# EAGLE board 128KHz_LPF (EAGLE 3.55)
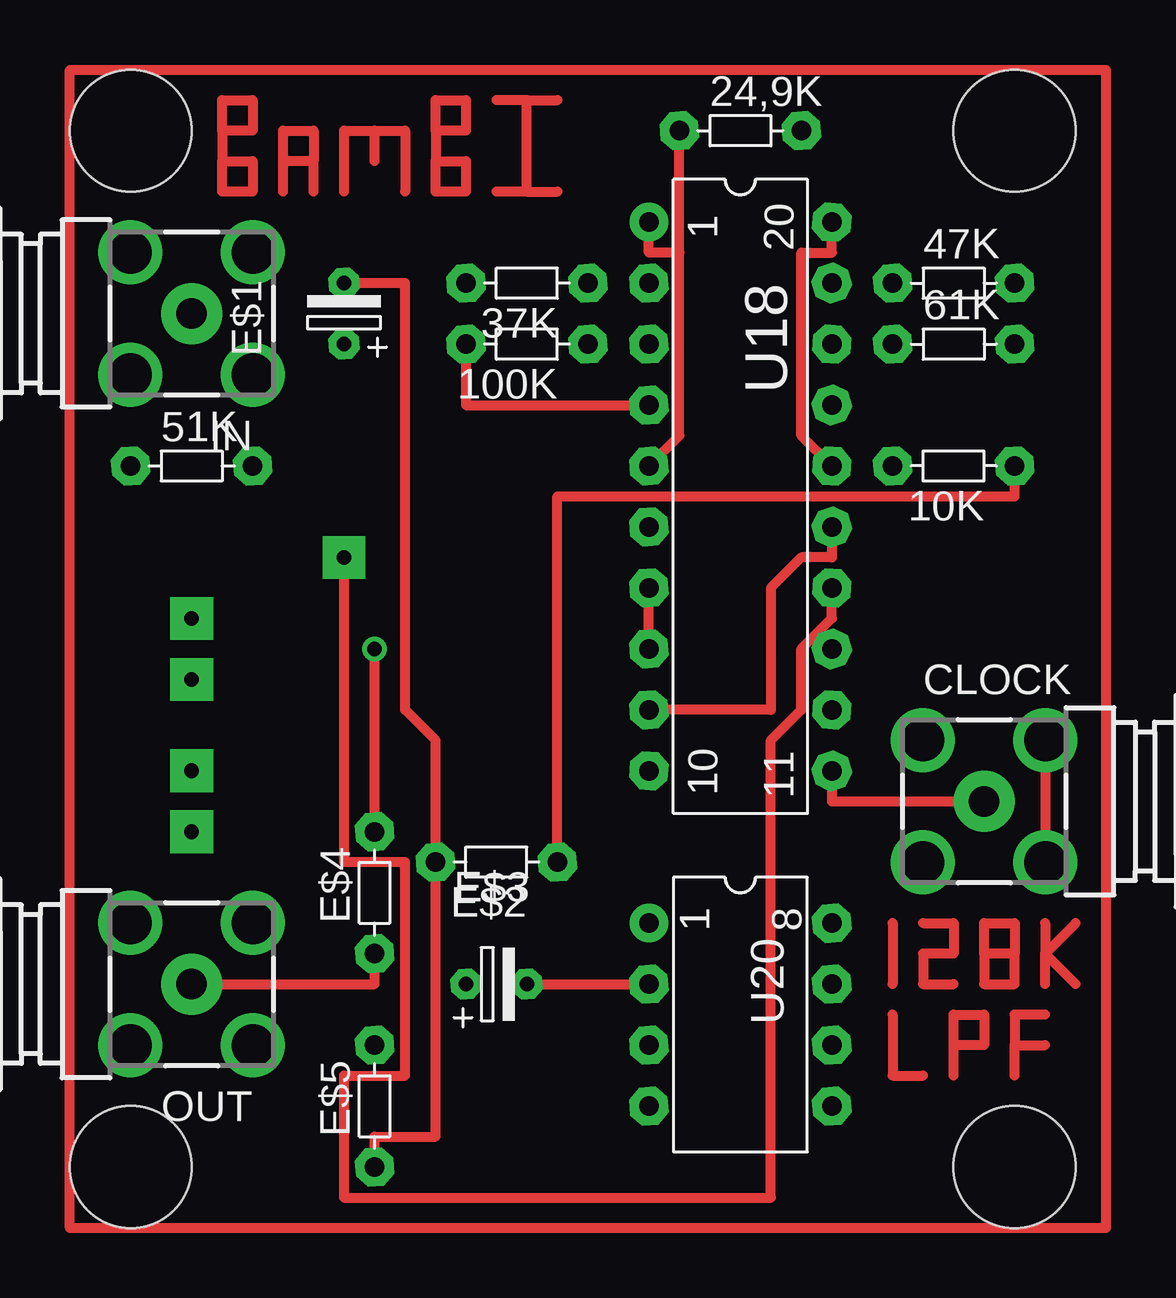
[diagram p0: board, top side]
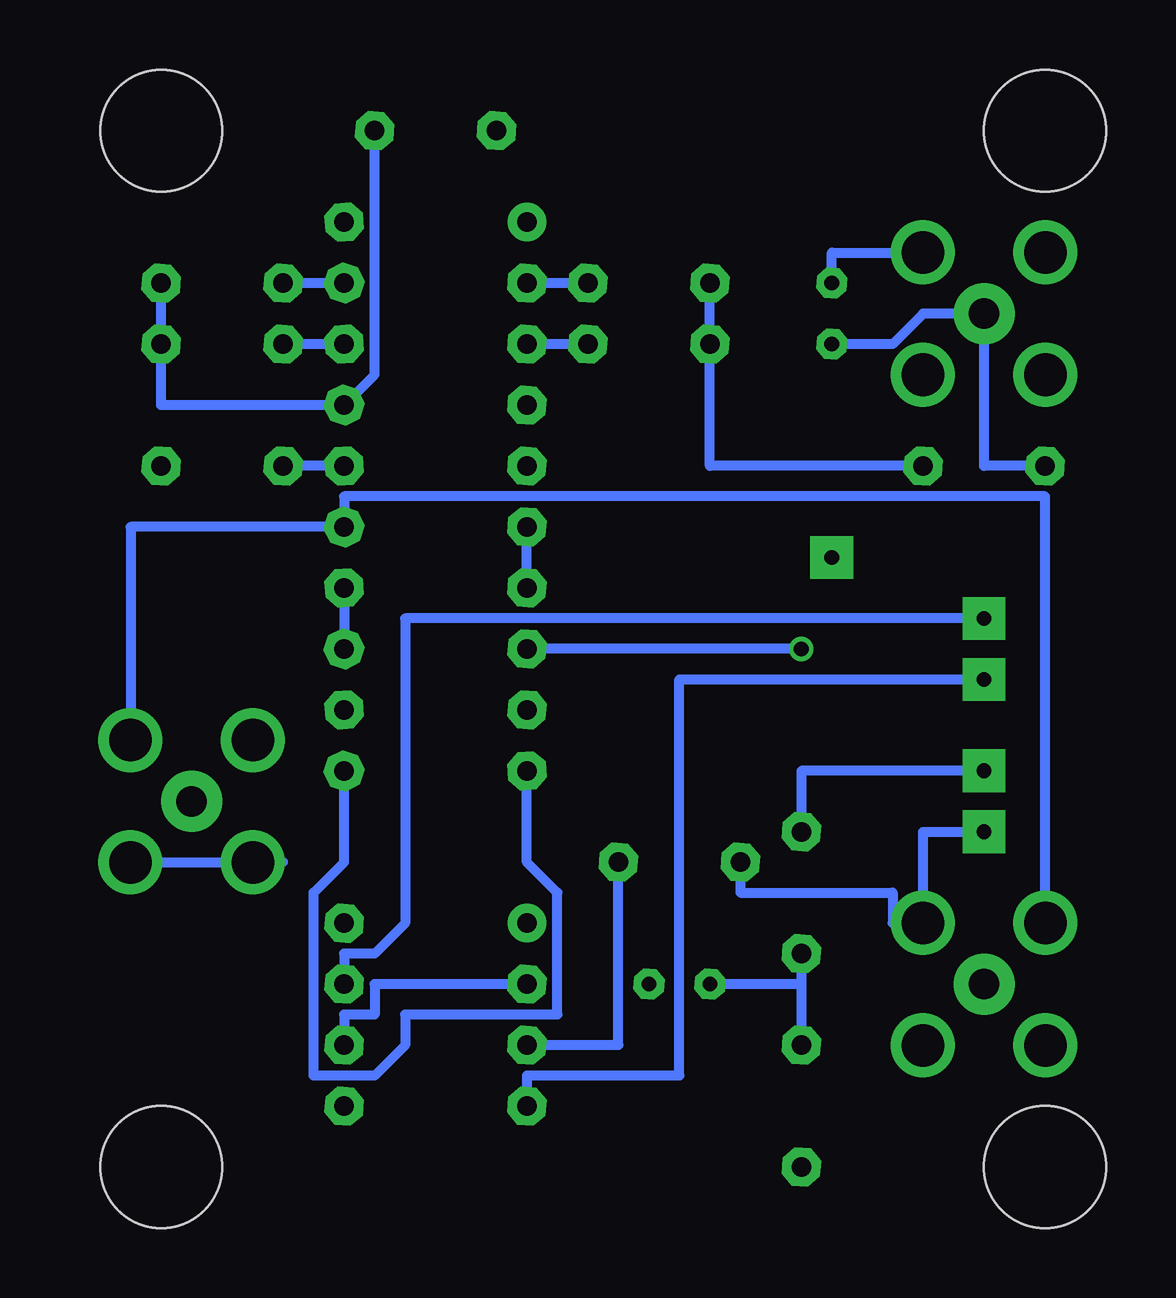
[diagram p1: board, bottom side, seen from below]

No outline drawn. Coordinates in mm, seen from the top.
Copper layers used: Top, Bottom
Holes 5.08 mm at 7.62,87.63 44.45,87.63 44.45,44.45 7.62,44.45

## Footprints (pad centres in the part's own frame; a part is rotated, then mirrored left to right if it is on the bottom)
5 = drill 0.813 pad 1.6 octagon:  -2.54,0;  2.54,0
-SMA-G = drill 1.27 pad 2.54 round:  0,0 | drill 1.778 pad 2.54 round:  -2.55,2.55;  2.55,2.55;  2.55,-2.55;  -2.55,-2.55
-2,5 = drill 0.61 pad 1.27 octagon:  -1.27,0;  1.27,0
L20 = drill 0.813 pad 1.6 round:  -11.43,-3.81 | drill 0.813 pad 1.6 octagon:  -8.89,-3.81;  -6.35,-3.81;  -3.81,-3.81;  -1.27,-3.81;  1.27,-3.81;  3.81,-3.81;  6.35,-3.81;  8.89,-3.81;  11.43,-3.81;  11.43,3.81;  8.89,3.81;  6.35,3.81;  3.81,3.81;  1.27,3.81;  -1.27,3.81;  -3.81,3.81;  -6.35,3.81;  -8.89,3.81;  -11.43,3.81
L08 = drill 0.813 pad 1.6 round:  -3.81,-3.81 | drill 0.813 pad 1.6 octagon:  -1.27,-3.81;  1.27,-3.81;  3.81,-3.81;  3.81,3.81;  1.27,3.81;  -1.27,3.81;  -3.81,3.81

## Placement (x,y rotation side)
10K  [5]  41.91,73.66 180 top
24,9K  [5]  33.02,87.63 0 top
37K  [5]  24.13,81.28 180 top
47K  [5]  41.91,81.28 0 top
51K  [5]  10.16,73.66 0 top
61K  [5]  41.91,78.74 0 top
100K  [5]  24.13,78.74 180 top
CLOCK  [-SMA-G]  43.18,59.69 0 top
E$1  [-2,5]  16.51,80.01 90 top
E$2  10K  [5]  22.86,57.15 180 top
E$3  [-2,5]  22.86,52.07 0 top
E$4  100K  [5]  17.78,55.88 90 top
E$5  100K  [5]  17.78,46.99 90 top
IN  [-SMA-G]  10.16,80.01 180 top
OUT  [-SMA-G]  10.16,52.07 180 top
U18  LMF100  [L20]  33.02,72.39 270 top
U20  741  [L08]  33.02,50.8 270 top

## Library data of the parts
10K 24,9K 37K 47K 51K 61K 100K E$1-E$5 = discrete
CLOCK IN OUT = con-coax
U18 = memory
U20 = 74xx

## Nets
51K: 51K. E$1. IN.
100K: 37K. 51K. 100K. U18.
+5: E$4. U18.
+12: U20.
-5: U18.
-12: U20.
GRND: E$1. E$2. E$5. IN. OUT.
S$2: 37K. U18.
S$3: 24,9K. 47K. 61K. U18.
S$4: 100K. U18.
S$5: 24,9K. U18.
S$6: 47K. U18.
S$7: 61K. U18.
S$8: 10K. U18.
S$9: 10K. E$2. U20.
S$10: E$3. E$4. E$5. OUT.
S$11: E$3. U20.
S$13: CLOCK. OUT. U18.
S$14: CLOCK. U18.

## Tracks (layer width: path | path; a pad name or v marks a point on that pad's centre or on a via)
51K
  Bottom 0.406: 16.51,78.74 13.97,78.74 12.7,80.01 10.16,80.01 10.16,73.66 7.62,73.66
100K
  Top 0.406: 29.21,76.2 21.59,76.2 100K.
  Bottom 0.406: 51K. 21.59,73.66 100K. 37K.
+5  (via drill 0.61 pad 1.02, 0.61 pad 1.78)
  Top 0.406: 29.21,66.04 29.21,68.58 | E$4. v17.78,66.04
  Bottom 0.406: v10.16,60.96 17.78,60.96 E$4. | 29.21,68.58 29.21,71.12 | v17.78,66.04 29.21,66.04
+12  (via drill 0.61 pad 1.78)
  Bottom 0.406: v10.16,67.31 34.29,67.31 34.29,54.61 35.56,53.34 36.83,53.34 36.83,52.07
-5  (via drill 0.61 pad 1.78)
  Top 0.406: v16.51,69.85 16.51,57.15 19.05,57.15 19.05,48.26 16.51,48.26 16.51,43.18 34.29,43.18 34.29,62.23 35.56,63.5 35.56,66.04 36.83,67.31 36.83,68.58
  Bottom 0.406: 36.83,68.58 36.83,66.04
-12  (via drill 0.61 pad 1.78)
  Bottom 0.406: v10.16,64.77 22.86,64.77 22.86,48.26 29.21,48.26 29.21,46.99
GRND  (via drill 0.61 pad 1.78)
  Top 0.406: E$1. 19.05,81.28 19.05,63.5 20.32,62.23 E$2. 20.32,45.72 17.78,45.72 17.78,44.45
  Bottom 0.406: E$1. 16.51,82.55 13.97,82.55 IN. | E$2. 20.32,55.88 13.97,55.88 13.97,54.61 OUT. 12.7,55.88 12.7,58.42 v10.16,58.42
S$1
  Top 0.406: 5.08,41.91 5.08,90.17 48.26,90.17 48.26,41.91 5.08,41.91
S$2
  Bottom 0.406: 26.67,81.28 29.21,81.28
S$3
  Bottom 0.406: 47K. 61K. 44.45,76.2 36.83,76.2 35.56,77.47 24,9K.
S$4
  Bottom 0.406: 26.67,78.74 29.21,78.74
S$5
  Top 0.406: 29.21,73.66 30.48,74.93 30.48,82.55 | 30.48,82.55 29.21,82.55 29.21,83.82 | 30.48,82.55 30.48,87.63
S$6
  Bottom 0.406: 36.83,81.28 39.37,81.28
S$7
  Bottom 0.406: 36.83,78.74 39.37,78.74
S$8
  Top 0.406: 36.83,73.66 35.56,74.93 35.56,82.55 36.83,82.55 U18.
  Bottom 0.406: 36.83,73.66 10K.
S$9
  Top 0.406: 44.45,73.66 44.45,72.39 25.4,72.39 25.4,57.15
  Bottom 0.406: 29.21,49.53 25.4,49.53 25.4,57.15
S$10
  Top 0.406: 17.78,53.34 17.78,52.07 10.16,52.07
  Bottom 0.406: 17.78,52.07 21.59,52.07 | 17.78,53.34 17.78,52.07 | 17.78,52.07 E$5.
S$11
  Top 0.406: E$3. 29.21,52.07
  Bottom 0.406: 29.21,52.07 35.56,52.07 35.56,50.8 36.83,50.8 36.83,49.53
S$12
  Top 0.406: 39.37,54.61 39.37,52.07
S$13
  Top 0.406: 29.21,63.5 34.29,63.5 34.29,68.58 35.56,69.85 36.83,69.85 36.83,71.12 | 45.73,62.24 45.72,62.23 45.72,57.15 45.73,57.14
  Bottom 0.406: 7.61,54.62 7.62,54.61 7.62,72.39 36.83,72.39 36.83,71.12 45.72,71.12 45.72,63.5 45.73,62.24 | CLOCK. 39.37,57.15 44.45,57.15 45.73,57.14
S$14
  Top 0.406: 36.83,60.96 36.83,59.69 43.18,59.69
  Bottom 0.406: 29.21,60.96 29.21,57.15 27.94,55.88 27.94,50.8 34.29,50.8 34.29,49.53 35.56,48.26 38.1,48.26 38.1,55.88 36.83,57.15 36.83,60.96
S$15
  Top 0.406: 40.64,54.61 41.91,54.61 41.91,53.34 40.64,53.34 40.64,52.07 41.91,52.07
S$16
  Top 0.406: 43.18,53.34 43.18,52.07 44.45,52.07 44.45,53.34 | 44.45,53.34 43.18,53.34 | 43.18,53.34 43.18,54.61 44.45,54.61 44.45,53.34
S$17
  Top 0.406: 45.72,54.61 45.72,53.34 | 45.72,52.07 45.72,53.34 | 46.99,54.61 45.72,53.34 | 45.72,53.34 46.99,52.07
S$18
  Top 0.406: 39.37,50.8 39.37,48.26 40.64,48.26
S$19
  Top 0.406: 41.91,48.26 41.91,49.53 | 41.91,49.53 41.91,50.8 43.18,50.8 43.18,49.53 41.91,49.53
S$20
  Top 0.406: 44.45,48.26 44.45,49.53 | 45.72,50.8 44.45,50.8 44.45,49.53 | 44.45,49.53 45.72,49.53
S$21
  Top 0.406: 11.43,86.36 11.43,85.09 12.7,85.09 12.7,86.36 11.43,86.36 | 11.43,87.63 11.43,88.9 12.7,88.9 12.7,87.63 11.43,87.63 | 11.43,87.63 11.43,86.36
S$22
  Top 0.406: 13.97,85.09 13.97,86.36 | 13.97,86.36 13.97,87.63 15.24,87.63 15.24,86.36 | 15.24,85.09 15.24,86.36 | 15.24,86.36 13.97,86.36
S$23
  Top 0.406: 16.51,85.09 16.51,87.63 17.78,87.63 | 17.78,86.36 17.78,87.63 | 17.78,87.63 19.05,87.63 19.05,85.09
S$24
  Top 0.406: 20.32,86.36 20.32,85.09 21.59,85.09 21.59,86.36 20.32,86.36 | 20.32,87.63 20.32,88.9 21.59,88.9 21.59,87.63 20.32,87.63 | 20.32,87.63 20.32,86.36
S$25
  Top 0.406: 24.13,88.9 22.86,88.9 | 24.13,85.09 24.13,88.9 | 24.13,85.09 22.86,85.09 | 24.13,85.09 25.4,85.09 | 24.13,88.9 25.4,88.9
